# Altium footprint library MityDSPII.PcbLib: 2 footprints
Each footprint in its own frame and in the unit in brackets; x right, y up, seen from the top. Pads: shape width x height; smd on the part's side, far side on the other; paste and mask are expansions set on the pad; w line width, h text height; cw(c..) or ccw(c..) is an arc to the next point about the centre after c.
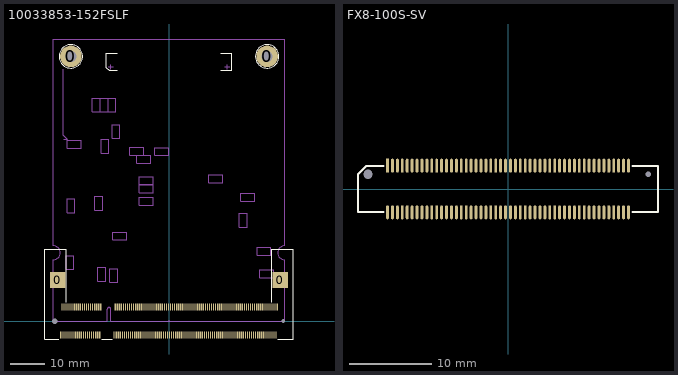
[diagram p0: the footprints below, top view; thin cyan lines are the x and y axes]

## 10033853-152FSLF [mm] "CONN SODIMM DDR2 200POS R/A SMD"
height 1.9
pads (206):
  round 0 hole 1.6 unplated: 0(-33.4,0)
  rect 4.5x4.6 smd: 0(-32.55,12) 0(32.55,12)
  round 6.35 hole 3.175: 0(-28.72,77.47) 0(28.72,77.47)
  round 0 hole 1.1 unplated: 0(33.4,0)
  rect 0.35x2 smd: 1(-31.65,-4.1) 2(-31.35,4.1) 3(-31.05,-4.1) 4(-30.75,4.1) 5(-30.45,-4.1) 6(-30.15,4.1) 7(-29.85,-4.1) 8(-29.55,4.1) 9(-29.25,-4.1) 10(-28.95,4.1) 11(-28.65,-4.1) 12(-28.35,4.1) 13(-28.05,-4.1) 14(-27.75,4.1) 15(-27.45,-4.1) 16(-27.15,4.1) 17(-26.85,-4.1) 18(-26.55,4.1) 19(-26.25,-4.1) 20(-25.95,4.1) 21(-25.65,-4.1) 22(-25.35,4.1) 23(-25.05,-4.1) 24(-24.75,4.1) 25(-24.45,-4.1) 26(-24.15,4.1) 27(-23.85,-4.1) 28(-23.55,4.1) 29(-23.25,-4.1) 30(-22.95,4.1) 31(-22.65,-4.1) 32(-22.35,4.1) 33(-22.05,-4.1) 34(-21.75,4.1) 35(-21.45,-4.1) 36(-21.15,4.1) 37(-20.85,-4.1) 38(-20.55,4.1) 39(-20.25,-4.1) 40(-19.95,4.1) 41(-16.05,-4.1) 42(-15.75,4.1) 43(-15.45,-4.1) 44(-15.15,4.1) 45(-14.85,-4.1) 46(-14.55,4.1) 47(-14.25,-4.1) 48(-13.95,4.1) 49(-13.65,-4.1) 50(-13.35,4.1) 51(-13.05,-4.1) 52(-12.75,4.1) 53(-12.45,-4.1) 54(-12.15,4.1) 55(-11.85,-4.1) 56(-11.55,4.1) 57(-11.25,-4.1) 58(-10.95,4.1) 59(-10.65,-4.1) 60(-10.35,4.1) 61(-10.05,-4.1) 62(-9.75,4.1) 63(-9.45,-4.1) 64(-9.15,4.1) 65(-8.85,-4.1) 66(-8.55,4.1) 67(-8.25,-4.1) 68(-7.95,4.1) 69(-7.65,-4.1) 70(-7.35,4.1) 71(-7.05,-4.1) 72(-6.75,4.1) 73(-6.45,-4.1) 74(-6.15,4.1) 75(-5.85,-4.1) 76(-5.55,4.1) 77(-5.25,-4.1) 78(-4.95,4.1) 79(-4.65,-4.1) 80(-4.35,4.1) 81(-4.05,-4.1) 82(-3.75,4.1) 83(-3.45,-4.1) 84(-3.15,4.1) 85(-2.85,-4.1) 86(-2.55,4.1) 87(-2.25,-4.1) 88(-1.95,4.1) 89(-1.65,-4.1) 90(-1.35,4.1) 91(-1.05,-4.1) 92(-0.75,4.1) 93(-0.45,-4.1) 94(-0.15,4.1) 95(0.15,-4.1) 96(0.45,4.1) 97(0.75,-4.1) 98(1.05,4.1) 99(1.35,-4.1) 100(1.65,4.1) 101(1.95,-4.1) 102(2.25,4.1) 103(2.55,-4.1) 104(2.85,4.1) 105(3.15,-4.1) 106(3.45,4.1) 107(3.75,-4.1) 108(4.05,4.1) 109(4.35,-4.1) 110(4.65,4.1) 111(4.95,-4.1) 112(5.25,4.1) 113(5.55,-4.1) 114(5.85,4.1) 115(6.15,-4.1) 116(6.45,4.1) 117(6.75,-4.1) 118(7.05,4.1) 119(7.35,-4.1) 120(7.65,4.1) 121(7.95,-4.1) 122(8.25,4.1) 123(8.55,-4.1) 124(8.85,4.1) 125(9.15,-4.1) 126(9.45,4.1) 127(9.75,-4.1) 128(10.05,4.1) 129(10.35,-4.1) 130(10.65,4.1) 131(10.95,-4.1) 132(11.25,4.1) 133(11.55,-4.1) 134(11.85,4.1) 135(12.15,-4.1) 136(12.45,4.1) 137(12.75,-4.1) 138(13.05,4.1) 139(13.35,-4.1) 140(13.65,4.1) 141(13.95,-4.1) 142(14.25,4.1) 143(14.55,-4.1) 144(14.85,4.1) 145(15.15,-4.1) 146(15.45,4.1) 147(15.75,-4.1) 148(16.05,4.1) 149(16.35,-4.1) 150(16.65,4.1) 151(16.95,-4.1) 152(17.25,4.1) 153(17.55,-4.1) 154(17.85,4.1) 155(18.15,-4.1) 156(18.45,4.1) 157(18.75,-4.1) 158(19.05,4.1) 159(19.35,-4.1) 160(19.65,4.1) 161(19.95,-4.1) 162(20.25,4.1) 163(20.55,-4.1) 164(20.85,4.1) 165(21.15,-4.1) 166(21.45,4.1) 167(21.75,-4.1) 168(22.05,4.1) 169(22.35,-4.1) 170(22.65,4.1) 171(22.95,-4.1) 172(23.25,4.1) 173(23.55,-4.1) 174(23.85,4.1) 175(24.15,-4.1) 176(24.45,4.1) 177(24.75,-4.1) 178(25.05,4.1) 179(25.35,-4.1) 180(25.65,4.1) 181(25.95,-4.1) 182(26.25,4.1) 183(26.55,-4.1) 184(26.85,4.1) 185(27.15,-4.1) 186(27.45,4.1) 187(27.75,-4.1) 188(28.05,4.1) 189(28.35,-4.1) 190(28.65,4.1) 191(28.95,-4.1) 192(29.25,4.1) 193(29.55,-4.1) 194(29.85,4.1) 195(30.15,-4.1) 196(30.45,4.1) 197(30.75,-4.1) 198(31.05,4.1) 199(31.35,-4.1) 200(31.65,4.1)
Top Overlay:
  circle w0.254: c28.72,77.47 r3.429
  circle w0.254: c-28.72,77.47 r3.429
  lines w0.254: -32.258,-5.232 -36.35,-5.232 -36.35,21 -30,21 -30,5.461 ; -19.685,-5.232 -16.637,-5.232 ; -15.15,73.347 -17.3,73.347 -17.467,73.347 -18.3,74.18 -18.3,74.65 -18.3,78.447 -15.15,78.447 ; 15.15,73.347 18.3,73.347 18.3,78.447 15.15,78.447 ; 30,5.461 30,21 36.35,21 36.35,-5.232 31.75,-5.232
Mechanical 1:
  lines w0.254: -30.959,73.631 -30.959,54.327 -29.845,53.213 -30.861,53.213 ; -17.817,74.4 -16.383,74.4 ; -17.1,73.743 -17.1,75.057 ; -17.05,3.5 -17.05,0 33.8,0 33.8,18 cw(c33.8,20) 33.8,22 33.8,82.55 -33.8,82.55 -33.8,22 cw(c-33.8,20) -33.8,18 -33.8,0 -18.05,0 -18.05,3.5 cw(c-17.55,3.5) -17.05,3.5 ; -0.254,0 0.254,0 ; 0,-0.254 0,0.254 ; 16.383,74.4 17.817,74.4 ; 17.1,73.746 17.1,75.06 ; -20.103,61.214 -20.103,65.278 ; -20.103,61.214 -17.817,61.214 ; -20.103,61.214 -22.389,61.214 -22.389,65.278 -20.103,65.278 ; -20.103,61.214 -20.103,65.278 ; -20.103,65.278 -17.817,65.278 ; -17.817,61.214 -17.817,65.278 ; -17.817,61.214 -15.531,61.214 -15.531,65.278 -17.817,65.278 ; -17.817,61.214 -17.817,65.278 ; -30.099,15.113 -27.813,15.113 -27.813,19.177 -30.099,19.177 -30.099,15.113 ; -29.845,31.75 -27.559,31.75 -27.559,35.814 -29.845,35.814 -29.845,31.75 ; -29.736,50.654 -29.736,52.94 -25.672,52.94 -25.672,50.654 -29.736,50.654 ; -21.717,32.512 -19.431,32.512 -19.431,36.576 -21.717,36.576 -21.717,32.512 ; -20.828,11.684 -18.542,11.684 -18.542,15.748 -20.828,15.748 -20.828,11.684 ; -19.849,49.149 -19.849,53.213 -17.563,53.213 -17.563,49.149 -19.849,49.149 ; -17.272,11.303 -17.272,15.367 -14.986,15.367 -14.986,11.303 -17.272,11.303 ; -16.637,53.467 -14.351,53.467 -14.351,57.531 -16.637,57.531 -16.637,53.467 ; -16.402,23.767 -16.402,26.053 -12.338,26.053 -12.338,23.767 -16.402,23.767 ; -11.525,48.532 -11.525,50.818 -7.461,50.818 -7.461,48.532 -11.525,48.532 ; -9.365,46.209 -9.365,48.495 -5.301,48.495 -5.301,46.209 -9.365,46.209 ; -8.654,33.89 -8.654,36.176 -4.59,36.176 -4.59,33.89 -8.654,33.89 ; -8.654,37.573 -8.654,39.859 -4.59,39.859 -4.59,37.573 -8.654,37.573 ; -8.654,39.986 -8.654,42.272 -4.59,42.272 -4.59,39.986 -8.654,39.986 ; -4.158,48.495 -4.158,50.781 -0.094,50.781 -0.094,48.495 -4.158,48.495 ; 11.665,40.531 11.665,42.817 15.729,42.817 15.729,40.531 11.665,40.531 ; 20.574,27.483 22.86,27.483 22.86,31.547 20.574,31.547 20.574,27.483 ; 21.063,35.07 21.063,37.356 25.127,37.356 25.127,35.07 21.063,35.07 ; 25.763,19.285 25.763,21.571 29.827,21.571 29.827,19.285 25.763,19.285 ; 26.525,12.681 26.525,14.967 30.589,14.967 30.589,12.681 26.525,12.681
  text "parts Keep-Out" at -31.75,53.594 h1.52
  text "Keep-Out for High Profile components" at 33.172,32.741 h1.27
  text "MityDSPII-pro outline" at -31.953,22.987 h1.27

## FX8-100S-SV [mm] "FX8 Series receptacle, 100 contacts"
height 3
pads (102):
  round 0 hole 1.1 unplated: 0(-17.1,1.8)
  round 0 hole 0.7 unplated: 0(17.1,1.8)
  rect 0.35x1.7 smd: 1(-14.7,2.85)
  oval 0.35x1.7 smd: 2(-14.7,-2.85) 3(-14.1,2.85) 4(-14.1,-2.85) 5(-13.5,2.85) 6(-13.5,-2.85) 7(-12.9,2.85) 8(-12.9,-2.85) 9(-12.3,2.85) 10(-12.3,-2.85) 11(-11.7,2.85) 12(-11.7,-2.85) 13(-11.1,2.85) 14(-11.1,-2.85) 15(-10.5,2.85) 16(-10.5,-2.85) 17(-9.9,2.85) 18(-9.9,-2.85) 19(-9.3,2.85) 20(-9.3,-2.85) 21(-8.7,2.85) 22(-8.7,-2.85) 23(-8.1,2.85) 24(-8.1,-2.85) 25(-7.5,2.85) 26(-7.5,-2.85) 27(-6.9,2.85) 28(-6.9,-2.85) 29(-6.3,2.85) 30(-6.3,-2.85) 31(-5.7,2.85) 32(-5.7,-2.85) 33(-5.1,2.85) 34(-5.1,-2.85) 35(-4.5,2.85) 36(-4.5,-2.85) 37(-3.9,2.85) 38(-3.9,-2.85) 39(-3.3,2.85) 40(-3.3,-2.85) 41(-2.7,2.85) 42(-2.7,-2.85) 43(-2.1,2.85) 44(-2.1,-2.85) 45(-1.5,2.85) 46(-1.5,-2.85) 47(-0.9,2.85) 48(-0.9,-2.85) 49(-0.3,2.85) 50(-0.3,-2.85) 51(0.3,2.85) 52(0.3,-2.85) 53(0.9,2.85) 54(0.9,-2.85) 55(1.5,2.85) 56(1.5,-2.85) 57(2.1,2.85) 58(2.1,-2.85) 59(2.7,2.85) 60(2.7,-2.85) 61(3.3,2.85) 62(3.3,-2.85) 63(3.9,2.85) 64(3.9,-2.85) 65(4.5,2.85) 66(4.5,-2.85) 67(5.1,2.85) 68(5.1,-2.85) 69(5.7,2.85) 70(5.7,-2.85) 71(6.3,2.85) 72(6.3,-2.85) 73(6.9,2.85) 74(6.9,-2.85) 75(7.5,2.85) 76(7.5,-2.85) 77(8.1,2.85) 78(8.1,-2.85) 79(8.7,2.85) 80(8.7,-2.85) 81(9.3,2.85) 82(9.3,-2.85) 83(9.9,2.85) 84(9.9,-2.85) 85(10.5,2.85) 86(10.5,-2.85) 87(11.1,2.85) 88(11.1,-2.85) 89(11.7,2.85) 90(11.7,-2.85) 91(12.3,2.85) 92(12.3,-2.85) 93(12.9,2.85) 94(12.9,-2.85) 95(13.5,2.85) 96(13.5,-2.85) 97(14.1,2.85) 98(14.1,-2.85) 99(14.7,2.85) 100(14.7,-2.85)
Top Overlay:
  lines w0.254: -15.2,-2.8 -18.3,-2.8 -18.3,1.8 -17.3,2.8 -15.2,2.8 ; 15.2,-2.8 18.3,-2.8 18.3,2.8 15.2,2.8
